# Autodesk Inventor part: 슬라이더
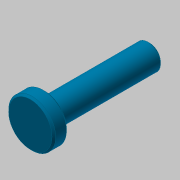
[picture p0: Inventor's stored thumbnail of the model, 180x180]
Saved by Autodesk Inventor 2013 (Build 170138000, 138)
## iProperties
Created: 2019-01
Part Number: 슬라이더
Material: 강철, 연강
Document SubType Name: Modeling
Designer: mduedu
Density: 1 g/cm^3
Author: mduedu
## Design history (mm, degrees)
sketch "스케치1"
  geometry: L1 (0, 0)-(8, 0); L2 (8, 0)-(8, 13); L3 (8, 13)-(0, 13); L4 (0, 13)-(0, 0); L5 (8, 0)-(66, 0); L6 (66, 0)-(66, 7); L7 (66, 7)-(8, 7); L8 (8, 7)-(8, 0)
  constraints: 16 end point, 4 parallel, 2 horizontal, 2 perpendicular
  dimensions: "d0" = 66 distance between parallel lines of L6 L4; "d2" = 8 distance of L2.end L3.end; "d3" = 26 diameter of L3 L1; "d4" = 14 diameter of L7 L5
revolve "회전1" sketch "스케치1" stored, may be unused: angle "d5" = 90 deg
chamfer "모따기1" distance "d6" = 1; stored, may be unused: second distance "d7" = 2, angle "d8" = 45 deg
hole "구멍1" diameter "d14" = 4.134; stored, may be unused: countersink angle "d18" = 60 deg, drill point angle "d20" = 118 deg; dims "d15" = 12, "d16" = 6.3, "d17" = 2, "d19" = 15, "d26" = 10, "d27" = 10
chamfer "모따기4" distance "d24" = 1; stored, may be unused: second distance "d25" = 2, angle "d28" = 30 deg
sketch "스케치2"
  geometry: L1 (66, 2.067)-(66, -2.067) reference; L2 (66, 0)-(64, 0); L3 (64, 0)-(64, 2.067); L4 (66, 3.222)-(66, 0); L5 (66, 3.222)-(64, 2.067); L6 (51, 2.067)-(66, 2.067) reference; 1 further point
  constraints: 8 end point, 1 horizontal, 1 midpoint, 1 parallel, 1 perpendicular, 1 point on line
  dimensions: "d29" = 2 horizontal distance of L4.start L3.end; "d31" = 30 deg angle of L2 L5
revolve "회전2" sketch "스케치2" stored, may be unused: angle "d33" = 90 deg
node "솔리드1"
